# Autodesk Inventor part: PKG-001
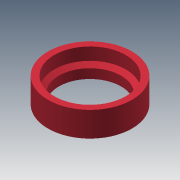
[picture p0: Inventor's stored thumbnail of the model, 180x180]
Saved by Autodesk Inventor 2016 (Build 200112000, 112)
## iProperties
Created: 2013-11
Part Number: PKG-001
Material: Nylon 6/6
Document SubType Name: Modeling
Designer: normanpa
Density: 1.13 g/cm^3
Appearance: 255,61,77
Description: OUTER GEAR PACKING
Mass: 14.5763 g
Surface Area: 67.734 cm^2
Volume: 12.8994 cm^3
Author: Autodesk
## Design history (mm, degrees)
sketch "Sketch1"
  geometry: L1 (23, 16)-(27, 16); L2 (27, 16)-(27, 0); L3 (27, 0)-(20, 0); L4 (20, 0)-(20, 6); L5 (20, 6)-(23, 8); L6 (23, 8)-(23, 16); L7 (0, 0)-(0, 16); 1 further point
  constraints: 14 end point, 1 coincident, 1 horizontal alignment, 1 parallel, 1 vertical
  dimensions: "d0" = 54 diameter of L2 L7; "d1" = 46 diameter of L6 L7; "d2" = 40 diameter of L4 L7; "d3" = 7 distance of L2.end L3.end; "d4" = 4 distance of L1.start L1.end; "d5" = 16 distance of L1.end L2.end; "d6" = 6 distance from line of L4.end L3; "d7" = 8 distance from line of L5.end L3
revolve "Revolution1" sketch "Sketch1" stored, may be unused: angle "d8" = 90 deg
body "Solid1"
